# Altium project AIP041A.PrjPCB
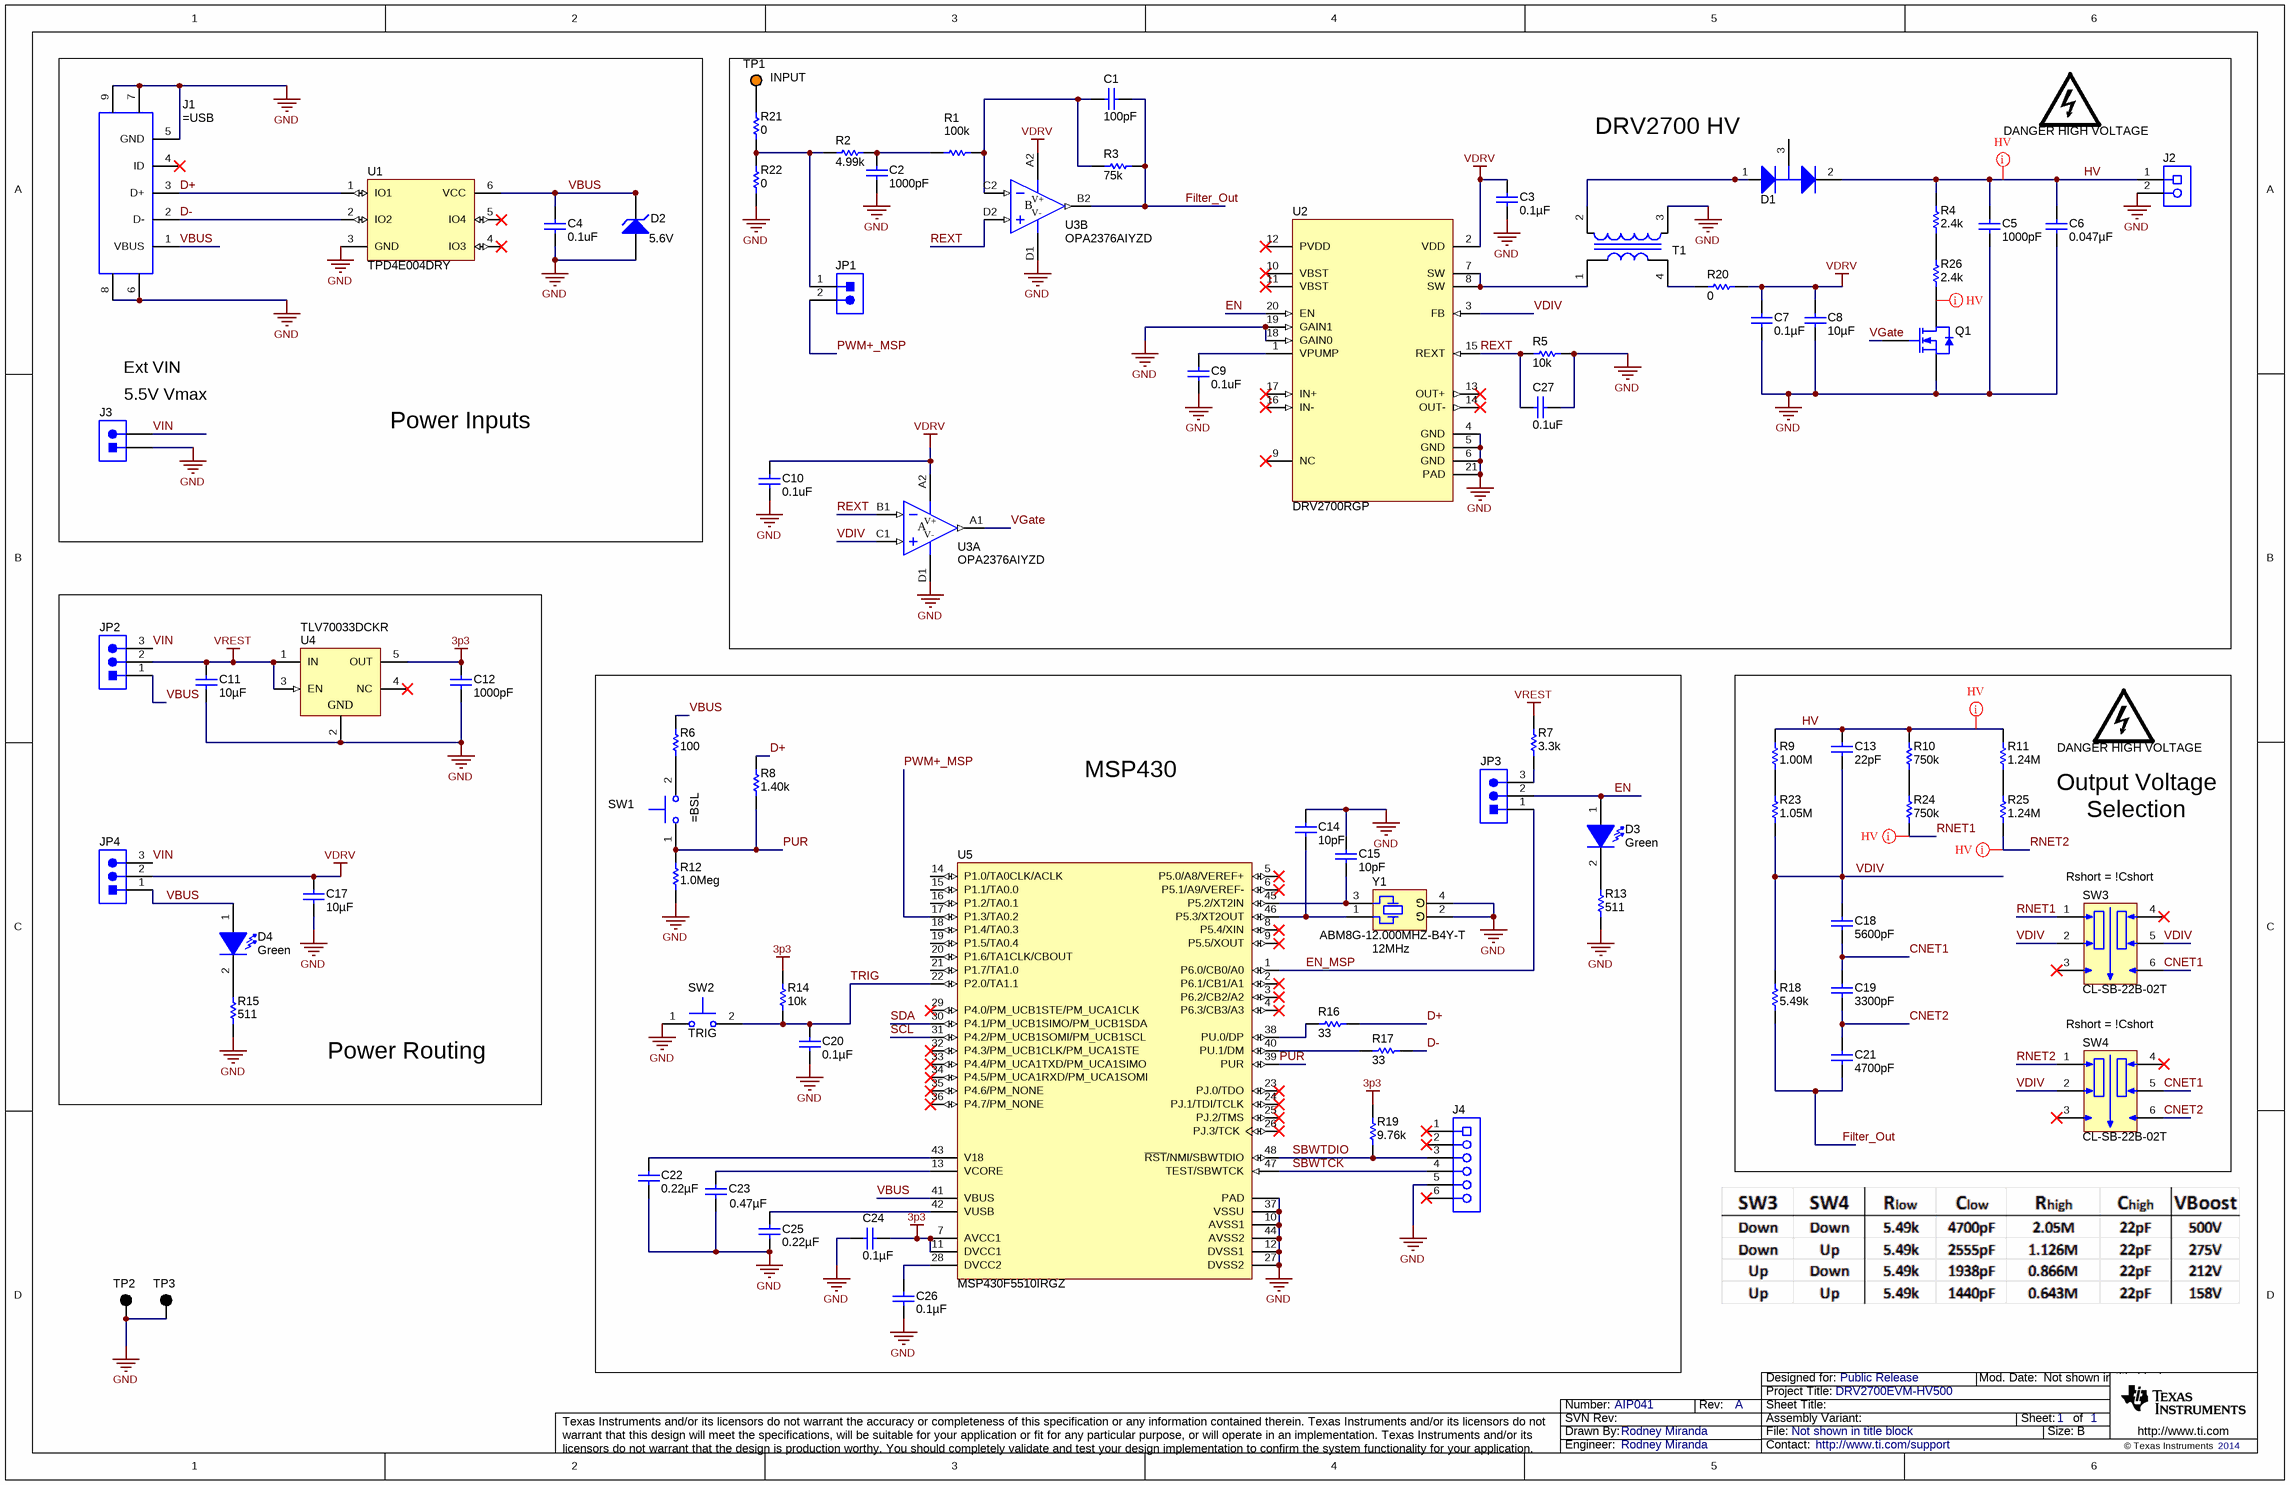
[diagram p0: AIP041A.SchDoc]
CopyrightYear: 2014; PCB_Layout: Rodney Miranda; PCB_Rev: A; PRJ_Customer: Public Release; PRJ_Engineer: Rodney Miranda; PRJ_Number: AIP041; PRJ_Title: DRV2700EVM-HV500; SCH_Rev: A; TechSupport: http://www.ti.com/support
2 sheets, 102 parts. Net scope: global (net labels, ports and power ports of the same name join across sheets).
Board file: AIP041A.PcbDoc
Sheets:
  AIP041A.SchDoc
  AIP041A_Hardware.SchDoc

## Sheet AIP041A.SchDoc
size 431 x 279 mm; Date: Not shown in title block; ApprovedBy: Not shown in title block; CheckedBy: Not shown in title block; Author: Not shown in title block; CompanyName: Not shown in title block; DrawnBy: Rodney Miranda; Engineer: Not shown in title block; Organization: Not shown in title block; Address1: Not shown in title block; Address2: Not shown in title block; Address3: Not shown in title block; Address4: Not shown in title block; DocumentNumber: 1; Revision: Use project parameter SCH_Rev; SheetNumber: 1; SheetTotal: 1; PageSetup: Record=PageOptions|CenterHorizontal=True|CenterVertical=True|PrintScale=0.62|XCorrection=1.00|YCorrection=1.00|PrintKind=0|BorderSize=5000000|LeftOffset=0|BottomOffset=0|Orientation=2|PaperLength=1000|PaperWidth=1000|Scale=100|PaperSource=15|PrintQuality=600|MediaType=1|DitherType=10|PaperKind=Letter (8.5 x 11")|PrintScaleMode=1

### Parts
(Parts that share a designator on the sheet are numbered #1, #2 ... from top to bottom, then left to right.)
C1  ValueDisplayed: 100pF  [0402]  (hidden comment: GRM1555C1H101JA01D)
C2  ValueDisplayed: 1000pF  [0402]  (hidden comment: GRM155R61A102KA01D)
C3  ValueDisplayed: 0.1µF  [0603]  (hidden comment: GRM188R71E104KA01D)
C4  value 0.1uF  [0402]  (hidden comment: GRM155R71C104JA88D)
C5  ValueDisplayed: 1000pF  [1206]  (hidden comment: GRM31B5C2J102JW01L)
C6  ValueDisplayed: 0.047µF  [1210M]  (hidden comment: GRM32DR72J473KW01L)
C7  ValueDisplayed: 0.1µF  [0603]  (hidden comment: GRM188R71E104KA01D)
C8  ValueDisplayed: 10µF  [0603]  (hidden comment: GRM188R61E106MA73)
C9  value 0.1uF  [0402]  (hidden comment: GRM155R71C104JA88D)
C10  value 0.1uF  [0402]  (hidden comment: GRM155R71C104JA88D)
C11  ValueDisplayed: 10µF  [0805_HV]  (hidden comment: 0805YD106MAT2A)
C12  ValueDisplayed: 1000pF  [0402]  (hidden comment: GRM155R60J102KA01D)
C13  ValueDisplayed: 22pF  [0805_HV]  (hidden comment: C0805C220KBRACTU)
C14  ValueDisplayed: 10pF  [0402]  (hidden comment: GRM1555C1H100JA01D)
C15  ValueDisplayed: 10pF  [0402]  (hidden comment: GRM1555C1H100JA01D)
C17  ValueDisplayed: 10µF  [0805_HV]  (hidden comment: 0805YD106MAT2A)
C18  ValueDisplayed: 5600pF  [0402]  (hidden comment: GRM155R71E562KA01D)
C19  ValueDisplayed: 3300pF  [0402]  (hidden comment: GRM155R71H332KA01D)
C20  ValueDisplayed: 0.1µF  [0402]  (hidden comment: C1005X5R0J104K)
C21  ValueDisplayed: 4700pF  [0603]  (hidden comment: GRM188R72A472KA01D)
C22  ValueDisplayed: 0.22µF  [0402]  (hidden comment: GRM155C80J224KE01D)
C23  ValueDisplayed: 0.47µF  [0603]  (hidden comment: C0603C474K8RACTU)
C24  ValueDisplayed: 0.1µF  [0402]  (hidden comment: C1005X5R0J104K)
C25  ValueDisplayed: 0.22µF  [0402]  (hidden comment: GRM155C80J224KE01D)
C26  ValueDisplayed: 0.1µF  [0402]  (hidden comment: C1005X5R0J104K)
C27  value 0.1uF  [0402]  (hidden comment: GRM155R71C104JA88D)
D1  MMBD3004S-7-F  [SOT-23]  (value not drawn)
D2  value 5.6V  [SOD-123]  (hidden comment: MMSZ5232B-7-F)
D3  value Green  [LED_LTST-C190_G]  (hidden comment: LTST-C190KGKT)
D4  value Green  [LED_LTST-C190_G]  (hidden comment: LTST-C190KGKT)
J1  (no value)  [MILLMAX_897-43-005-00-100001]
J2  1751248  [CONN_1751248]  (value not drawn)
J3  1725656  [CONN_1725656]  (value not drawn)
J4  LPPB061NGCN-RC  [SULLINS_LPPB061NGCN-RC]  (value not drawn)
JP1  5-146261-1  [CONN_5-146261-1]  (value not drawn)
JP2  5-146278-3  [TE_5-146278-3]  (value not drawn)
JP3  5-146278-3  [TE_5-146278-3]  (value not drawn)
JP4  5-146278-3  [TE_5-146278-3]  (value not drawn)
LOGO?#1  DANGER HIGH VOLTAGE  [IEC_HighVoltage_Medium]  (graphical)
LOGO?#2  DANGER HIGH VOLTAGE  [IEC_HighVoltage_Medium]  (graphical)
Q1  BSS127 H6327  [SOT-23]  (value not drawn)
R1  ValueDisplayed: 100k  [0402]  (hidden comment: CRCW0402100KFKED)
R2  ValueDisplayed: 4.99k  [0402]  (hidden comment: CRCW04024K99FKED)
R3  ValueDisplayed: 75k  [0402]  (hidden comment: CRCW040275K0JNED)
R4  ValueDisplayed: 2.4k  [0805_HV]  (hidden comment: CRCW08052K40JNEA)
R5  ValueDisplayed: 10k  [0402]  (hidden comment: CRCW040210K0JNED)
R6  value 100  [0402]  (hidden comment: CRCW0402100RFKED)
R7  value 3.3k  [0402]  (hidden comment: CRCW04023K30JNED)
R8  value 1.40k  [0402]  (hidden comment: CRCW04021K40FKED)
R9  ValueDisplayed: 1.00M  [0805_HV]  (hidden comment: CRCW08051M00FKEA)
R10  ValueDisplayed: 750k  [0805_HV]  (hidden comment: RT0805BRD07750KL)
R11  ValueDisplayed: 1.24M  [0805_HV]  (hidden comment: CRCW08051M24FKEA)
R12  value 1.0Meg  [0402]  (hidden comment: CRCW04021M00JNED)
R13  value 511  [0402]  (hidden comment: CRCW0402511RFKED)
R14  value 10k  [0402]  (hidden comment: CRCW040210K0JNED)
R15  value 511  [0402]  (hidden comment: CRCW0402511RFKED)
R16  value 33  [0402]  (hidden comment: CRCW040233R0JNED)
R17  value 33  [0402]  (hidden comment: CRCW040233R0JNED)
R18  ValueDisplayed: 5.49k  [0402]  (hidden comment: CRCW04025K49FKED)
R19  value 9.76k  [0402]  (hidden comment: CRCW04029K76FKED)
R20  ValueDisplayed: 0  [0402]  (hidden comment: RC0402JR-070RL)
R21  ValueDisplayed: 0  [0603]  (hidden comment: CRCW06030000Z0EA)
R22  ValueDisplayed: 0  [0603]  (hidden comment: CRCW06030000Z0EA)
R23  ValueDisplayed: 1.05M  [0805_HV]  (hidden comment: CRCW08051M05FKEA)
R24  ValueDisplayed: 750k  [0805_HV]  (hidden comment: RT0805BRD07750KL)
R25  ValueDisplayed: 1.24M  [0805_HV]  (hidden comment: CRCW08051M24FKEA)
R26  ValueDisplayed: 2.4k  [0805_HV]  (hidden comment: CRCW08052K40JNEA)
SW1  (no value)  [SW_TL1015AF160QG]
SW2  TRIG  [SW_TL1015AF160QG]
SW3  CL-SB-22B-02T  [SW_CL-SB-22B-02]
SW4  CL-SB-22B-02T  [SW_CL-SB-22B-02]
T1  ATB322515-0110  [XFMR_ATB3215]  (value not drawn)
TP1  INPUT  [Keystone5013]
TP2  (no value)  [Keystone5011]
TP3  (no value)  [Keystone5011]
U1  TPD4E004DRY  [DRY0006A]
U2  DRV2700RGP  [RGP0020D]
U3  OPA2376AIYZD  [YZD0008ANAP]  (parts A,B of 2)
U4  TLV70033DCKR  [DCK0005A_N]
U5  MSP430F5510IRGZ  [RGZ0048A]
Y1  ABM8G-12.000MHZ-B4Y-T  Frequency: 12MHz  [XTAL_NX3225SA]

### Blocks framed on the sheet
Power Inputs: C4 D2 J1 J3 U1
DRV2700 HV: C1-C3 C5-C10 C27 D1 J2 JP1 LOGO?#1 Q1 R1-R5 R20-R22 R26 T1 TP1 U2 U3
Power Routing: C11 C12 C17 D4 JP2 JP4 R15 U4
MSP430: C14 C15 C20 C22-C26 D3 J4 JP3 R6-R8 R12-R14 R16 R17 R19 SW1 SW2 U5 Y1

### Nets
3p3: C12.1 C24.2 R14.2 R19.2 U4.5(OUT) U5.7(AVCC1) U5.11(DVCC1)
GND: C2.2 C3.2 C4.2 C5.2 C6.2 C7.2 C8.2 C9.2 C10.2 C11.2 C12.2 C14.1 C15.1 C17.2 C20.2 C22.2 C23.2 C24.1 C25.2 C26.1 C27.2 D2.2(A) J1.5(GND) J1.6 J1.7 J1.8 J1.9 J2.2 J3.1 J4.5 Q1.2(S) R5.2 R12.1 R13.1 R15.1 R22.1 SW2.1 T1.3 TP2.1 TP3.1 U1.3(GND) U2.4(GND) U2.5(GND) U2.6(GND) U2.18(GAIN0) U2.19(GAIN1) U2.21(PAD) U3.D1(V-) U4.2(GND) U5.10(AVSS1) U5.12(DVSS1) U5.27(DVSS2) U5.37(VSSU) U5.44(AVSS2) U5.49(PAD) Y1.2(GND) Y1.4(GND)
VDRV: C3.1 C7.1 C8.1 C10.1 C17.1 JP4.2 R20.2 U2.2(VDD) U3.A2(V+)
VREST: C11.1 JP2.2 R7.2 U4.1(IN) U4.3(EN)
CNET1: C18.2 C19.1 SW3.6 SW4.5(C)
CNET2: C19.2 C21.1 SW4.6
D+: J1.3(D+) R8.2 R16.2 U1.1(IO1)
D-: J1.2(D-) R17.2 U1.2(IO2)
EN: D3.1(A) JP3.2 U2.20(EN)
EN_MSP: JP3.1 U5.1(P6.0/CB0/A0)
Filter_Out: C1.1 C21.2 R3.1 R18.1 U3.B2(OUT)
HV: C5.1 C6.1 C13.1 D1.2(K) J2.1 R4.2 R9.2 R10.2 R11.2
PUR: R8.1 R12.2 SW1.1 U5.39(PUR)
PWM+_MSP: JP1.2 U5.17(P1.3/TA0.2)
REXT: C27.1 R5.1 U2.15(REXT) U3.B1(IN-) U3.D2(IN+)
RNET1: R24.1 SW3.1
RNET2: R25.1 SW4.1
SBWTCK: J4.4 U5.47(TEST/SBWTCK)
SBWTDIO: J4.3 R19.1 U5.48(~{RST}/NMI/SBWTDIO)
SCL: U5.31(P4.2/PM_UCB1SOMI/PM_UCB1SCL)
SDA: U5.30(P4.1/PM_UCB1SIMO/PM_UCB1SDA)
TRIG: C20.1 R14.1 SW2.2 U5.22(P2.0/TA1.1)
VBUS: C4.1 D2.1(K) D4.1(A) J1.1(VBUS) JP2.1 JP4.1 R6.2 U1.6(VCC) U5.41(VBUS)
VDIV: C13.2 C18.1 R18.2 R23.1 SW3.2(C) SW3.5(C) SW4.2(C) U2.3(FB) U3.C1(IN+)
VGate: Q1.1(G) U3.A1(OUT)
VIN: J3.2 JP2.3 JP4.3
NetC1_2: C1.2 R1.2 R3.2 U3.C2(IN-)
NetC2_1: C2.1 R1.1 R2.2
NetC9_1: C9.1 U2.1(VPUMP)
NetC14_2: C14.2 U5.46(P5.3/XT2OUT) Y1.1
NetC15_2: C15.2 U5.45(P5.2/XT2IN) Y1.3
NetC22_1: C22.1 U5.43(V18)
NetC23_1: C23.1 U5.13(VCORE)
NetC25_1: C25.1 U5.42(VUSB)
NetC26_2: C26.2 U5.28(DVCC2)
NetD1_1: D1.1(A) T1.2
NetD3_2: D3.2(K) R13.2
NetD4_2: D4.2(K) R15.2
NetJP1_1: JP1.1 R2.1 R21.1 R22.2
NetJP3_3: JP3.3 R7.1
NetQ1_3: Q1.3(D) R26.1
NetR4_1: R4.1 R26.2
NetR6_1: R6.1 SW1.2
NetR9_1: R9.1 R23.2
NetR10_1: R10.1 R24.2
NetR11_1: R11.1 R25.2
NetR16_1: R16.1 U5.38(PU.0/DP)
NetR17_1: R17.1 U5.40(PU.1/DM)
NetR20_1: R20.1 T1.4
NetR21_2: R21.2 TP1.1
NetT1_1: T1.1 U2.7(SW) U2.8(SW)

Not connected (* = marked no-connect by the designer): D1 3(C); J1 4(ID)*; J4 1* 2* 6*; SW3 3* 4*; SW4 3* 4*; U1 4(IO3)* 5(IO4)*; U2 9(NC)* 10(VBST)* 11(VBST)* 12(PVDD)* 13(OUT+)* 14(OUT-)* 16(IN-)* 17(IN+)*; U4 4(NC)*; U5 2(P6.1/CB1/A1)* 3(P6.2/CB2/A2)* 4(P6.3/CB3/A3)* 5(P5.0/A8/VEREF+)* 6(P5.1/A9/VEREF-)* 8(P5.4/XIN)* 9(P5.5/XOUT)* 14(P1.0/TA0CLK/ACLK) 15(P1.1/TA0.0) 16(P1.2/TA0.1) 18(P1.4/TA0.3) 19(P1.5/TA0.4) 20(P1.6/TA1CLK/CBOUT) 21(P1.7/TA1.0) 23(PJ.0/TDO)* 24(PJ.1/TDI/TCLK)* 25(PJ.2/TMS)* 26(PJ.3/TCK)* 29(P4.0/PM_UCB1STE/PM_UCA1CLK)* 32(P4.3/PM_UCB1CLK/PM_UCA1STE)* 33(P4.4/PM_UCA1TXD/PM_UCA1SIMO)* 34(P4.5/PM_UCA1RXD/PM_UCA1SOMI)* 35(P4.6/PM_NONE)* 36(P4.7/PM_NONE)*

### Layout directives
net class HV: HV, NetQ1_3, RNET1, RNET2

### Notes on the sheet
- Ext VIN
- (near J3) 5.5V Vmax
- Output Voltage
- Selection
- (near SW3) Rshort = !Cshort
- Rshort = !Cshort

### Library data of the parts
C1 = GRM1555C1H101JA01D: CAP, CERM, 100 pF, 50 V, +/- 5%, C0G/NP0, 0402; Manufacturer: MuRata; Polarized: N; CompType: Capacitor; Value: 100pF; U/M: EA; Cap_F: 0.0000000001; Tolerance_%: 5; Value1: Unknown; VDC_V: 50; Value2: 50V; TaMin_C: -55; TaMax_C: 125
C2 = GRM155R61A102KA01D: CAP, CERM, 1000 pF, 10 V, +/- 10%, X5R, 0402; Manufacturer: MuRata; Polarized: N; CompType: Capacitor; Value: 1000pF; U/M: EA; Cap_F: 0.000000001; Tolerance_%: 10; Value1: Unknown; Value2: 10V; TaMin_C: -55; TaMax_C: 85
C3 C7 = GRM188R71E104KA01D: CAP, CERM, 0.1 µF, 25 V, +/- 10%, X7R, 0603; Manufacturer: MuRata; Polarized: N; CompType: Capacitor; Value: 0.1uF; U/M: EA; Cap_F: 0.0000001; Tolerance_%: 10; Value1: Unknown; VDC_V: 25; Value2: 25V; TaMin_C: -55; TaMax_C: 125
C4 C9 C10 C27 = 0402YC132KAT2A: CAP CER 0.1UF 16V 5% X7R 0402; Manufacturer: Murata Electronics North America; Polarized: N; CompType: Capacitor; U/M: EA; Cap_F: 0.0000000013; Tolerance_%: 10; VDC_V: 16; TaMin_C: -55; TaMax_C: 125
C5 = GRM31B5C2J102JW01L: CAP, CERM, 1000 pF, 630 V, +/- 5%, C0G/NP0, 1206; Manufacturer: MuRata; Polarized: N; CompType: Capacitor; Value: 1000pF; U/M: EA; Cap_F: 0.000000001; Tolerance_%: 5; Value1: Unknown; VDC_V: 630; Value2: 630V; TaMin_C: -55; TaMax_C: 125
C6 = GRM32DR72J473KW01L: CAP, CERM, 0.047 µF, 630 V, +/- 10%, X7R, 1210; Manufacturer: MuRata; Polarized: N; CompType: Capacitor; Value: 0.047uF; U/M: EA; Cap_F: 0.000000047; Tolerance_%: 10; Value1: Unknown; VDC_V: 630; Value2: 630V; TaMin_C: -55; TaMax_C: 125; Cap_Case: 1210
C8 = GRM188R61E106MA73: CAP, CERM, 10 µF, 25 V, +/- 20%, X5R, 0603; Manufacturer: MuRata; Polarized: N; CompType: Capacitor; Value: 10uF; U/M: EA; Cap_F: 0.00001; Tolerance_%: 20; Value1: Unknown; VDC_V: 25; Value2: 25V; TaMin_C: -55; TaMax_C: 85
C11 C17 = 0805YD106MAT2A: CAP, CERM, 10uF, 16V, +/-20%, X5R, 0805; Manufacturer: AVX; Polarized: N; CompType: Capacitor; U/M: EA; Cap_F: 0.00001; Tolerance_%: 20; Value1: Unknown; VDC_V: 16; TaMin_C: -55; TaMax_C: 85; Cap_Case: 0805
C12 = GRM155R60J102KA01D: CAP, CERM, 1000pF, 6.3V, +/-10%, X5R, 0402; Manufacturer: MuRata; Polarized: N; CompType: Capacitor; U/M: EA; Cap_F: 0.000000001; Tolerance_%: 10; Value1: Unknown; VDC_V: 6.3; TaMin_C: -55; TaMax_C: 85
C13 = C0805C220KBRACTU: CAP, CERM, 22 pF, 630 V, +/- 10%, X7R, 0805_140; Manufacturer: Kemet; Polarized: N; CompType: Capacitor; Value: 22pF; U/M: EA; Cap_F: 0.000000000022; Tolerance_%: 10; Value1: Unknown; VDC_V: 630; Value2: 630V; TaMin_C: -55; TaMax_C: 125
C14 C15 = GRM1555C1H100JA01D: CAP, CERM, 10pF, 50V, +/-5%, C0G/NP0, 0402; Manufacturer: MuRata; Polarized: N; CompType: Capacitor; U/M: EA; Cap_F: 0.00000000001; Tolerance_%: 5; Value1: Unknown; VDC_V: 50; TaMin_C: -55; TaMax_C: 125
C18 = GRM155R71E562KA01D: CAP, CERM, 5600 pF, 25 V, +/- 10%, X7R, 0402; Manufacturer: MuRata; Polarized: N; CompType: Capacitor; Value: 5600pF; U/M: EA; Cap_F: 0.0000000056; Tolerance_%: 10; Value1: Unknown; VDC_V: 25; Value2: 25V; TaMin_C: -55; TaMax_C: 125
C19 = GRM155R71H332KA01D: CAP, CERM, 3300 pF, 50 V, +/- 10%, X7R, 0402; Manufacturer: MuRata; Polarized: N; CompType: Capacitor; Value: 3300pF; U/M: EA; Cap_F: 0.0000000033; Tolerance_%: 10; Value1: Unknown; VDC_V: 50; Value2: 50V; TaMin_C: -55; TaMax_C: 125
C20 C24 C26 = C1005X5R0J104K: CAP, CERM, 0.1uF, 6.3V, +/-10%, X5R, 0402; Manufacturer: TDK; Polarized: N; CompType: Capacitor; U/M: EA; Cap_F: 0.0000001; Tolerance_%: 10; ESR_Ohm: 0.0186; Value1: 0.0186 ohm; VDC_V: 6.3; TaMin_C: -55; TaMax_C: 85
C21 = GRM188R72A472KA01D: CAP, CERM, 4700 pF, 100 V, +/- 10%, X7R, 0603; Manufacturer: MuRata; Polarized: N; CompType: Capacitor; Value: 4700pF; U/M: EA; Cap_F: 0.0000000047; Tolerance_%: 10; Value1: Unknown; VDC_V: 100; Value2: 100V; TaMin_C: -55; TaMax_C: 125
C22 C25 = GRM155C80J224KE01D: CAP, CERM, 0.22uF, 6.3V, +/-10%, X6S, 0402; Manufacturer: MuRata; Polarized: N; CompType: Capacitor; U/M: EA; Cap_F: 0.00000022; Tolerance_%: 10; Value1: Unknown; VDC_V: 6.3; TaMin_C: -55; TaMax_C: 105
C23 = C0603C474K8RACTU: CAP, CERM, 0.47uF, 10V, +/-10%, X7R, 0603; Manufacturer: Kemet; Polarized: N; CompType: Capacitor; U/M: EA; Cap_F: 0.00000047; Tolerance_%: 10; TaMin_C: -55; TaMax_C: 125
D1 = MMBD3004S-7-F: Diode, Switching, 350 V, 0.225 A, SOT-23; Manufacturer: Diodes Inc.; U/M: EA; Vf_V: 1.25; Value: 350V; Value1: 0.225A; Value2: 1.25V; Io_A: 0.225; Vr_V: 350; TJmax_C: 150; RJC_CperW: 357
D2 = MMSZ5232B-7-F: Diode, Zener, 5.6V, 500 mW, SOD-123; Manufacturer: Diodes Inc.; SymbolCreator: a0412235; U/M: EA; Power_W: 0.5; Vz_V: 5.6; Value1: 0.5W; RJA_CperW: 350
D3 D4 = LTST-C190KGKT: LED, Green, SMD; Manufacturer: Lite-On; Type: AlInGaP; Vf_V: 2; Value2: 2V; Io_A: 0.03; Tjmax_C: 85; Value1: W; U/M: EA
J1 = 897-43-005-00-100001: Connector, USB Mini B; Manufacturer: Mill-Max; SymbolCreator: a0799628; U/M: EA
J2 = 1751248: Conn Term Block, 2POS, 3.5mm, TH; Manufacturer: Phoenix Contact; SymbolCreator: a0412235; Value: 2x1; CompType: Terminal Block; U/M: EA
J3 = 1725656: Header, 2 Pos, 6A, 63V, TH; Manufacturer: Phoenix Contact; SymbolCreator: a0412235; U/M: EA
J4 = LPPB061NGCN-RC: Receptacle, 50mil, 6x1, R/A, TH; Manufacturer: Sullins Connector Solutions; SymbolCreator: a0411947; U/M: EA
JP1 = 5-146261-1: Header, 100mil, 2x1, Gold, TH; Manufacturer: TE Connectivity; SymbolCreator: a0412235; U/M: EA
JP2-JP4 = 5-146278-3: Header, 100mil, 3x1, Tin, TH; Manufacturer: TE Connectivity; SymbolCreator: a0799628; U/M: EA
LOGO?#1 LOGO?#2 = IEC_HighVoltage: IEC 61010-1 High Voltage Warning; SymbolCreator: a0412235
Q1 = BSS127 H6327: MOSFET, N-CH, 600 V, 0.021 A, SOT-23; Manufacturer: Infineon Technologies; Alternate Manufacturer: None; U/M: EA; ChType: N; Value: 600V; VdsMax_V: 600; Value1: 600 ohm; Value2: 0.07 nC; QgTyp_nC: 0.07; Vgs_V: 20; IdsMax_A: 0.021
R1 = CRCW0402100KFKED: RES, 100 k, 1%, 0.063 W, 0402; Manufacturer: Vishay-Dale; CompType: Resistor; Value: 100k; Res_ohm: 100000; Tolerance_%: 1; Power_W: 0.063; Value2: 0.063W; VDC_V: 50; TempCo: 100 ppm/C; EIA_Code: E96; U/M: EA
R2 = CRCW04024K99FKED: RES, 4.99 k, 1%, 0.063 W, 0402; Manufacturer: Vishay-Dale; CompType: Resistor; Value: 4.99k; Res_ohm: 4990; Value_Code: 4k99; Tolerance_%: 1; Power_W: 0.063; Value2: 0.063W; VDC_V: 50; TempCo: 100 ppm/C; EIA_Code: E96; U/M: EA
R3 = CRCW040275K0JNED: RES, 75 k, 5%, 0.063 W, 0402; Manufacturer: Vishay-Dale; CompType: Resistor; Value: 75k; Res_ohm: 75000; Value_Code: 75k0; Tolerance_%: 5; Power_W: 0.063; Value2: 0.063W; VDC_V: 50; TempCo: 200 ppm/C; EIA_Code: E24; U/M: EA
R4 R26 = CRCW08052K40JNEA: RES, 2.4 k, 5%, 0.125 W, 0805; Manufacturer: Vishay-Dale; CompType: Resistor; Value: 2.4k; Res_ohm: 2400; Value_Code: 2k40; Tolerance_%: 5; Power_W: 0.125; Value2: 0.125W; VDC_V: 150; TempCo: 200 ppm/C; EIA_Code: E24; U/M: EA
R5 = CRCW040210K0JNED: RES, 10 k, 5%, 0.063 W, 0402; Manufacturer: Vishay-Dale; CompType: Resistor; Value: 10k; Res_ohm: 10000; Value_Code: 10k0; Tolerance_%: 5; Power_W: 0.063; Value2: 0.063W; VDC_V: 50; TempCo: 200 ppm/C; EIA_Code: E24; U/M: EA
R6 = CRCW0402100RFKED: RES, 100 ohm, 1%, 0.063W, 0402; Manufacturer: Vishay-Dale; CompType: Resistor; Value_Code: 100R; Tolerance_%: 1; Power_W: 0.063; VDC_V: 50; TempCo: 100 ppm/C; EIA_Code: E96; U/M: EA
R7 = CRCW04023K30JNED: RES, 3.3k ohm, 5%, 0.063W, 0402; Manufacturer: Vishay-Dale; CompType: Resistor; Res_ohm: 3300; Value_Code: 3k30; Tolerance_%: 5; Power_W: 0.063; VDC_V: 50; TempCo: 200 ppm/C; EIA_Code: E24; U/M: EA
R8 = CRCW04021K40FKED: RES, 1.40k ohm, 1%, 0.063W, 0402; Manufacturer: Vishay-Dale; CompType: Resistor; Res_ohm: 1400; Value_Code: 1k40; Tolerance_%: 1; Power_W: 0.063; VDC_V: 50; TempCo: 100 ppm/C; EIA_Code: E96; U/M: EA
R9 = CRCW08051M00FKEA: RES, 1.00 M, 1%, 0.125 W, 0805; Manufacturer: Vishay-Dale; CompType: Resistor; Value: 1.00Meg; Res_ohm: 1000000; Value_Code: 1M00; Tolerance_%: 1; Power_W: 0.125; Value2: 0.125W; VDC_V: 150; TempCo: 100 ppm/C; EIA_Code: E96; U/M: EA
R10 R24 = RT0805BRD07750KL: RES, 750 k, 0.1%, 0.125 W, 0805; Manufacturer: Yageo America; CompType: Resistor; Value: 750k; Res_ohm: 750000; Tolerance_%: 0.1; Power_W: 0.125; Value2: 0.125W; VDC_V: 150; TempCo: 25 ppm/C; EIA_Code: E192; U/M: EA
R11 R25 = CRCW08051M24FKEA: RES, 1.24 M, 1%, 0.125 W, 0805; Manufacturer: Vishay-Dale; CompType: Resistor; Value: 1.24Meg; Res_ohm: 1240000; Value_Code: 1M24; Tolerance_%: 1; Power_W: 0.125; Value2: 0.125W; VDC_V: 150; TempCo: 100 ppm/C; EIA_Code: E96; U/M: EA
R12 = CRCW04021M00JNED: RES, 1.0Meg ohm, 5%, 0.063W, 0402; Manufacturer: Vishay-Dale; CompType: Resistor; Res_ohm: 1000000; Value_Code: 1M00; Tolerance_%: 5; Power_W: 0.063; VDC_V: 50; TempCo: 200 ppm/C; EIA_Code: E24; U/M: EA
R13 R15 = CRCW0402511RFKED: RES, 511 ohm, 1%, 0.063W, 0402; Manufacturer: Vishay-Dale; CompType: Resistor; Value_Code: 511R; Tolerance_%: 1; Power_W: 0.063; VDC_V: 50; TempCo: 100 ppm/C; EIA_Code: E96; U/M: EA
R14 = CRCW040210K0JNED: RES, 10k ohm, 5%, 0.063W, 0402; Manufacturer: Vishay-Dale; CompType: Resistor; Res_ohm: 10000; Value_Code: 10k0; Tolerance_%: 5; Power_W: 0.063; VDC_V: 50; TempCo: 200 ppm/C; EIA_Code: E24; U/M: EA
R16 R17 = CRCW040233R0JNED: RES, 33 ohm, 5%, 0.063W, 0402; Manufacturer: Vishay-Dale; CompType: Resistor; Value_Code: 33R0; Tolerance_%: 5; Power_W: 0.063; VDC_V: 50; TempCo: 200 ppm/C; EIA_Code: E24; U/M: EA
R18 = CRCW04025K49FKED: RES, 5.49 k, 1%, 0.063 W, 0402; Manufacturer: Vishay-Dale; CompType: Resistor; Value: 5.49k; Res_ohm: 5490; Value_Code: 5k49; Tolerance_%: 1; Power_W: 0.063; Value2: 0.063W; VDC_V: 50; TempCo: 100 ppm/C; EIA_Code: E96; U/M: EA
R19 = CRCW04029K76FKED: RES, 9.76k ohm, 1%, 0.063W, 0402; Manufacturer: Vishay-Dale; CompType: Resistor; Res_ohm: 9760; Value_Code: 9k76; Tolerance_%: 1; Power_W: 0.063; VDC_V: 50; TempCo: 100 ppm/C; EIA_Code: E96; U/M: EA
R20 = RC0402JR-070RL: RES, 0, 5%, 0.063 W, 0402; Manufacturer: Yageo America; CompType: Resistor; Value: 0; Value_Code: 0000; Tolerance_%: 5; Power_W: 0.063; Value2: 0.063W; VDC_V: 50; TempCo: 200 ppm/C; EIA_Code: E24; U/M: EA
R21 R22 = CRCW06030000Z0EA: RES, 0, 5%, 0.1 W, 0603; Manufacturer: Vishay-Dale; CompType: Resistor; Value: 0; Value_Code: 0000; Tolerance_%: 5; Power_W: 0.1; Value2: 0.1W; VDC_V: 75; TempCo: 200 ppm/C; EIA_Code: E24; U/M: EA
R23 = CRCW08051M05FKEA: RES, 1.05 M, 1%, 0.125 W, 0805; Manufacturer: Vishay-Dale; CompType: Resistor; Value: 1.05Meg; Res_ohm: 1050000; Value_Code: 1M05; Tolerance_%: 1; Power_W: 0.125; Value2: 0.125W; VDC_V: 150; TempCo: 100 ppm/C; EIA_Code: E96; U/M: EA
SW1 SW2 = TL1015AF160QG: Switch, Tactile, SPST-NO, 0.05A, 12V, SMT; Manufacturer: E-Switch; SymbolCreator: a0412235; VDC_V: 12; SwitchFunction: Off-Mom; PositionCount: 1; CurrentRating_mA: 50
SW3 SW4 = CL-SB-22B-02T: Switch, Slide, DPDT, 0.2A, GULL, 12V, SMD; Manufacturer: Copal Electronics; SymbolCreator: x0208325; VDC_V: 12; SwitchFunction: On-On; PositionCount: 2; CurrentRating_mA: 200
T1 = ATB322515-0110: Transformer, Xenon Flash, 7uH, SMT; Manufacturer: TDK; SymbolCreator: a0411947; DCR_Ohm: 0.5; U/M: EA
TP1 = 5013: Test Point, Multipurpose, Orange, TH; Manufacturer: Keystone; CompType: Test Point Loop; U/M: EA
TP2 TP3 = 5011: Test Point, Multipurpose, Black, TH; Manufacturer: Keystone; CompType: Test Point Loop; U/M: EA
U1 = TPD4E004DRY: 4-CHANNEL ESD-PROTECTION ARRAY FOR HIGH-SPEED DATA INTERFACES, DRY006A; Alternate Manufacturer: None; Manufacturer: Texas Instruments; SymbolCreator: a0411947; CompType: IC; U/M: EA
U2 = DRV2700RGP: Piezo Driver with Integrated Boost Converter, RGP0020D; Manufacturer: Texas Instruments; SymbolCreator: Altium; CompType: IC; U/M: EA
U3 = OPA2376AIYZD: Low-Noise, Low Quiescent Current, Precision Operational Amplifier e-trim Series; Manufacturer: Texas Instruments; SymbolCreator: a0799628; CompType: IC; U/M: EA
U4 = TLV70033DCKR: Single Output LDO, 200 mA, Fixed 3.3 V Output, 2 to 5.5 V Input, with Low IQ, 5-pin SC70 (DCK), -40 to 125 degC, Green (RoHS & no Sb/Br); Manufacturer: Texas Instruments; Alternate Manufacturer: None; Alternate PartNumber: Equivalent; Accuracy(%): 2; Fixed Output Options(V): 3.3; Iout(Max)(A): 0.2; Iq(Typ)(mA): 0.03; SubFamily: Single Channel LDO; Vdo(Typ)(mV): 175; Vin(Max)(V): 5.5
U5 = MSP430F5510IRGZ: Mixed Signal MicroController, RGZ0048A; Alternate Manufacturer: None; Manufacturer: Texas Instruments; ADC: 10-bit SAR; ADC Channels: 8; Brown Out Reset: Yes; DMA: 3; Eco-Plan: Green (RoHS & no Sb/Br); Flash(KB): 32; Frequency(MHz): 25; GPIO: 47; Multiplier: 32x32; SRAM(B): 4096; SubFamily: 5 Series; Timers - 16-bit: 4; USB: 1; USCI_A (UART/LIN/IrDA/SPI): 2; SymbolCreator: Altium/a0412235; CompType: IC; U/M: EA
Y1 = ABM8G-12.000MHZ-B4Y-T: CRYSTAL 12.000MHZ 10PF SMD; Manufacturer: Abracon Corportation; SymbolCreator: a0412235; U/M: EA; TaMin_C: -20; TaMax_C: 70; Frequency Stability: ±30ppm

## Sheet AIP041A_Hardware.SchDoc
size 431 x 279 mm; Date: Not shown in title block; ApprovedBy: Not shown in title block; CheckedBy: Not shown in title block; Author: Not shown in title block; CompanyName: Not shown in title block; Engineer: Not shown in title block; Organization: Not shown in title block; Address1: Not shown in title block; Address2: Not shown in title block; Address3: Not shown in title block; Address4: Not shown in title block; DocumentNumber: 1; Revision: Use project parameter SCH_Rev; SheetNumber: 1; SheetTotal: 1; PageSetup: Record=PageOptions|CenterHorizontal=True|CenterVertical=True|PrintScale=1.00|XCorrection=1.00|YCorrection=1.00|PrintKind=0|BorderSize=5000000|LeftOffset=0|BottomOffset=0|Orientation=2|PaperLength=1000|PaperWidth=1000|Scale=100|PaperSource=15|PrintQuality=600|MediaType=1|DitherType=10|PaperKind=Letter|PrintScaleMode=1
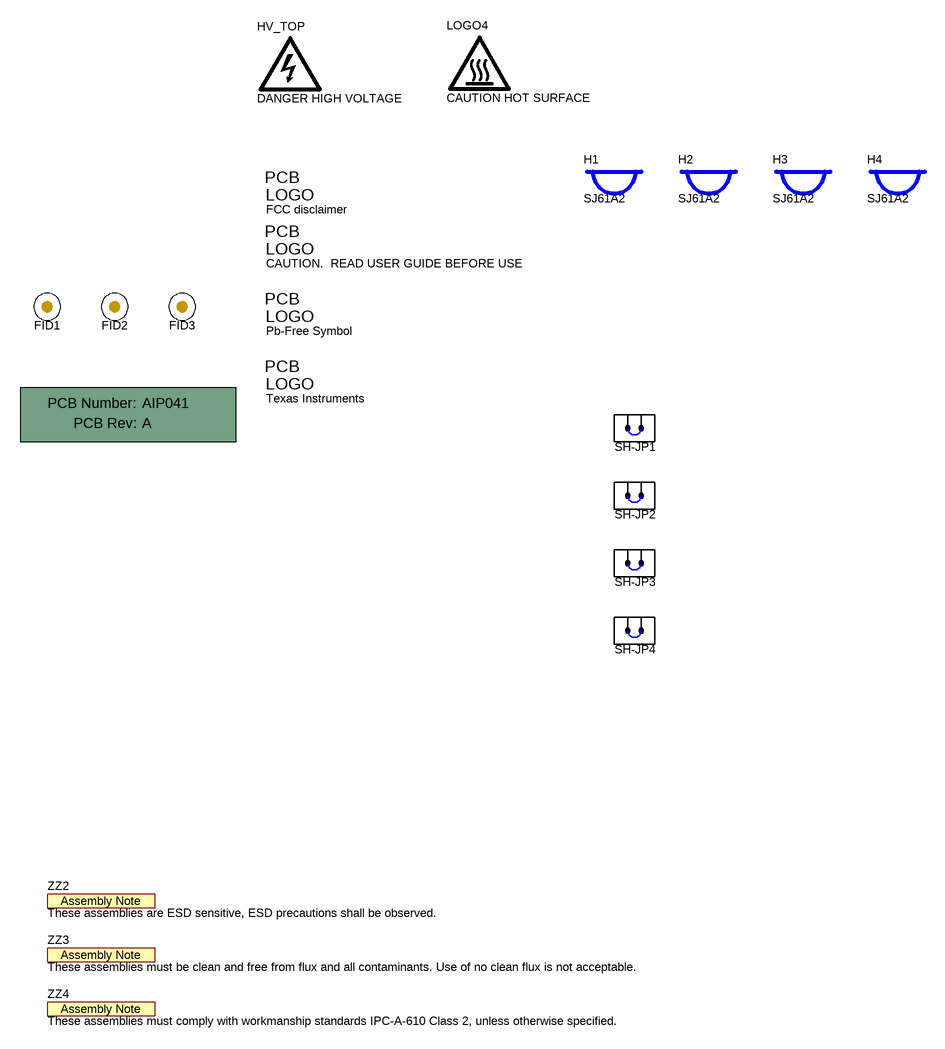
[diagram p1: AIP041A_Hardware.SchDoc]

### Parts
!PCB  Printed Circuit Board  (value not drawn)  (mechanical)
CAUTION_TOP  CAUTION.  READ USER GUIDE BEFORE USE  [IEC_Caution_Small]  (no BOM)
FID1  Fiducial  [Fiducial10-20]  (value not drawn)
FID2  Fiducial  [Fiducial10-20]  (value not drawn)
FID3  Fiducial  [Fiducial10-20]  (value not drawn)
H1  SJ61A2  [Bumpon_SJ61A2]
H2  SJ61A2  [Bumpon_SJ61A2]
H3  SJ61A2  [Bumpon_SJ61A2]
H4  SJ61A2  [Bumpon_SJ61A2]
HV_TOP  DANGER HIGH VOLTAGE  [IEC_HighVoltage_Small]  (no BOM)
Logo1  Texas Instruments  [TI_Horizontal_Overlay_Small]  (no BOM)
Logo2  Pb-Free Symbol  [Pb-Free_Overlay_Small]  (no BOM)
Logo3  FCC disclaimer  [FCC_disclaimer]  (no BOM)
LOGO4  CAUTION HOT SURFACE  [IEC_HotSurface_Small]  (no BOM)
SH-JP1  2SN-BK-G  [2SN-BK-G]  (value not drawn)
SH-JP2  2SN-BK-G  [2SN-BK-G]  (value not drawn)
SH-JP3  2SN-BK-G  [2SN-BK-G]  (value not drawn)
SH-JP4  2SN-BK-G  [2SN-BK-G]  (value not drawn)
ZZ2  These assemblies are ESD sensitive, ESD precautions shall be observed.  [AssemblyNote]  (no BOM)
ZZ3  These assemblies must be clean and free from flux and all contaminants. Use of no clean flux is not acceptable.  [AssemblyNote]  (no BOM)
ZZ4  These assemblies must comply with workmanship standards IPC-A-610 Class 2, unless otherwise specified.  [AssemblyNote]  (no BOM)

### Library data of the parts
!PCB = PCB: Manufacturer: Any; PartNumber: AIP041; SymbolCreator: a0412235
CAUTION_TOP = IEC_Caution: IEC 61010-1 Caution Warning; SymbolCreator: a0412235
FID1-FID3 = Fiducial: Fiducial mark.  There is nothing to buy or mount.; SymbolCreator: codlsc
H1-H4 = SJ61A2: Bumpon, Hemisphere, 0.375 X 0.235, Black; Manufacturer: 3M; SymbolCreator: a0412235
HV_TOP = IEC_HighVoltage: as LOGO?#1 on sheet AIP041A
Logo1 = TI_Logo: Texas Instrument Corporate Signature; SymbolCreator: a0412235
Logo2 = Pb-Free: SymbolCreator: a0412235
Logo3 = FCC_disclaimer: SymbolCreator: codlsc
LOGO4 = IEC_HotSurface: IEC 61010-1 Hot Surface Warning; SymbolCreator: a0412235
SH-JP1-SH-JP4 = 2SN-BK-G: Shunt, 2mm, Gold plated, Black; Manufacturer: Samtec; Value: 1x2; Note: You can "mate" this to a header by matching the designator.  i.e. use SH-J3 for header J3
ZZ2-ZZ4 = AssemblyNote: SymbolCreator: codlsc

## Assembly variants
001: not fitted !PCB C27 FID1 FID2 FID3 R22 ZZ2 ZZ3 ZZ4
